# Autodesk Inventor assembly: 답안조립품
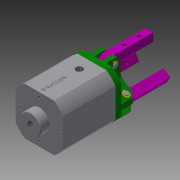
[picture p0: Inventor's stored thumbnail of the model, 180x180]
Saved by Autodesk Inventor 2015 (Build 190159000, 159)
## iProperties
Created: 2020-02
Part Number: 답안조립품
Document SubType Name: Assembly
Designer: 1026954
Author: 1026954
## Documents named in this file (13)
- C:\Users\1026954\Desktop\700206V1013\답안조립품.iam
- C:\Users\1026954\Desktop\700206V1013\E링.ipt
- C:\Users\1026954\Desktop\700206V1013\O-RING 12x16.ipt
- C:\Users\1026954\Desktop\700206V1013\O-RING 18x22.ipt
- C:\Users\1026954\Desktop\700206V1013\O-RING 34x40.ipt
- C:\Users\1026954\Desktop\700206V1013\로드.ipt
- C:\Users\1026954\Desktop\700206V1013\본체.ipt
- C:\Users\1026954\Desktop\700206V1013\본체헤드.ipt
- C:\Users\1026954\Desktop\700206V1013\볼트 M4.ipt
- C:\Users\1026954\Desktop\700206V1013\피스톤.ipt
- C:\Users\1026954\Desktop\700206V1013\핀 A.ipt
- C:\Users\1026954\Desktop\700206V1013\핀 B.ipt
- C:\Users\1026954\Desktop\700206V1013\핑거.ipt
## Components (20 placed, 8 different names)
1. E링:1
2. O-RING 12x16:1
3. O-RING 18x22:1
4. O-RING 34x40:1
5. 피스톤:1
6. 핀 A:1
7. 핀 B:1
8. 핑거:1 — 각도:1
9. 핀 B:2
10. 핀 B:3
11. 핑거:2 — 각도:3
12. 핑거:3 — 각도:2, 각도:4
13. 핀 A:2
14. 핀 A:3
15. E링:2
16. E링:3
17. E링:4
18. E링:5
19. E링:6
20. O-RING 34x40:2
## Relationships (4: Angle 4)
- 각도:1 [Angle]: 핑거:1
- 각도:2 [Angle]: 핑거:3
- 각도:3 [Angle]: 핑거:2
- 각도:4 [Angle]: 핑거:3
